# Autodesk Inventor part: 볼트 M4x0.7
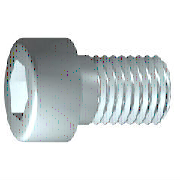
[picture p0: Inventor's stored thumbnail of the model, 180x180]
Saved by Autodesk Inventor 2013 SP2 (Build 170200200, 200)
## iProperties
IsCustomPart: 0
Created: 2015-12
Part Number: 볼트 M4x0.7
Material: 강철, 연강
Description: 6각머리 태핑 나사
Document SubType Name: Modeling
Standard: KS B 1003
Designer: mdu
Standards Organization: KS
Language: ko-KR
Size Designation: M 4 x 12
Categories: <MemberInstance><Categories><Category DisplayName="조임쇠" InternalName="e4da775c-781d-43d5-af7c-5136215cf5a6" Mnemonic="FSTN"><Category DisplayName="볼트" InternalN
Density: 1 g/cm^3
Author: mdu
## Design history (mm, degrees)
sketch "스케치1"
  geometry: L1 (-1, 0)-(12, 0); L2 (12, 0)-(12, 2); L3 (12, 2)-(1.75, 2); L4 (1.75, 2)-(1.32, 2); L5 (1.32, 2)-(0, 2); L6 (0, 2)-(0, 3.5); L7 (0, 3.5)-(-4, 3.5); L8 (-4, 3.5)-(-4, 1.732); L9 (-4, 1.732)-(-2, 1.732); L10 (-2, 1.732)-(-1, 0); L11 (-7.2, 0)-(15.2, 0) reference; L12 (0, -0.7)-(0, 4.2) reference; L13 (1.75, 2)-(0, 2)
  constraints: 22 end point, 6 parallel, 2 collinear, 2 perpendicular, 1 horizontal, 1 point on line
  dimensions: "d1" = 10.25 distance from line of L3.end L2 (= GEL); "d2" = 0.42952 distance of L4.end L3.end (computed from GAL); "d3" = 4 distance between parallel lines of L8 L6 (= KOH); "d4" = 2 distance of L8.end L9.end (= INTI); "d5" = 60 deg angle of L10 L1; "d6" = 4 diameter of L3 L1 (= GD); "d7" = 4 diameter of L5 L1 (= BDM); "d8" = 3.4641 diameter of L9 L1 (= 1.1547 x SW); "d9" = 7 diameter of L7 L1 (= KOD); "d26" = 12 distance between parallel lines of L12 L2 (= NLG)
revolve "본체" sketch "스케치1" stored, may be unused: angle "d10" = 90 deg
sketch "스케치2"
  geometry: L1 (0, -4.9)-(0, 4.9) reference; L2 (-4.9, 0)-(4.9, 0) reference; L3 (1.732, 0)-(0.866, -1.5); L4 (0.866, -1.5)-(-0.866, -1.5); L5 (-0.866, -1.5)-(-1.732, 0); L6 (-1.732, 0)-(-0.866, 1.5); L7 (-0.866, 1.5)-(0.866, 1.5); L8 (0.866, 1.5)-(1.732, 0); 2 further points
  constraints: 12 end point, 1 coincident, 1 horizontal alignment, 1 point on line, 12 other
extrude "슬롯" join sketch "스케치2" stored distance "d11" = 10; taper "d12" = 0 deg
workplane "Work Plane1"
fillet "Fillet2" dims "d30" = 0.1 (= R)
body "Solid1"
fillet "모깎기1" dims "d17" = 0.4 (= RR)
feature "스레드" dims "d13" = 10.25 (= GEL), "d14" = 0
chamfer "모따기1" distance "d15" = 0.42941 (= -0.5 x SPD + 0.5 x GD); stored, may be unused: second distance "d16" = 0.42941 (= GUL), angle "d27" = 45 deg
other parameters: "GD" = 4 (= NND) [user parameter; used in 2 equation terms], "NLG" = 12 [user parameter; used in 1 equation term], "GEL" = 10.25 [user parameter; used in 2 equation terms], "KOD" = 7 [user parameter; used in 1 equation term], "KOH" = 4 [user parameter; used in 1 equation term], "INTI" = 2 [user parameter; used in 1 equation term], "GAL" = 0.42941 (= 0.61345 x PTC) [user parameter; used in 1 equation term], "GUL" = 0.42941 (= 0.61345 x PTC) [user parameter; used in 1 equation term], "BDM" = 4 (= NND) [user parameter; used in 1 equation term], "SW" = 3 [user parameter; used in 2 equation terms], "RR" = 0.4 [user parameter; used in 1 equation term], "SPD" = 3.14117 (= NND - 1.2269 x PTC) [user parameter; used in 1 equation term], "d19" = 0, "d28" = 0, "d29" = 0, "R" = 0.1 [user parameter; used in 1 equation term], "PHH" = 0.2 [user parameter], "GD1" = 3.14117 (= THREADDIA - 1.2269 x PTC) [user parameter], "THREADDIA" = 4 [user parameter; used in 1 equation term], "FAWI" = 45 deg [user parameter], "TPU" = 14.28571 (computed from PTC) [user parameter], "PTC" = 0.7 [user parameter; used in 5 equation terms], "NND" = 4 [user parameter; used in 3 equation terms], "TOA" = 30 deg [user parameter], "E0" = 3.465 (= 1.155 x SW) [user parameter]
